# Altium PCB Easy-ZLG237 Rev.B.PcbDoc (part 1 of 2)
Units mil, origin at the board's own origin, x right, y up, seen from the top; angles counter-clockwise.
Board outline 3937.01 x 2559.06 mil, 2 copper layers (Top Layer, Bottom Layer); 111 components, 102 nets, 447 pads, 498 vias.
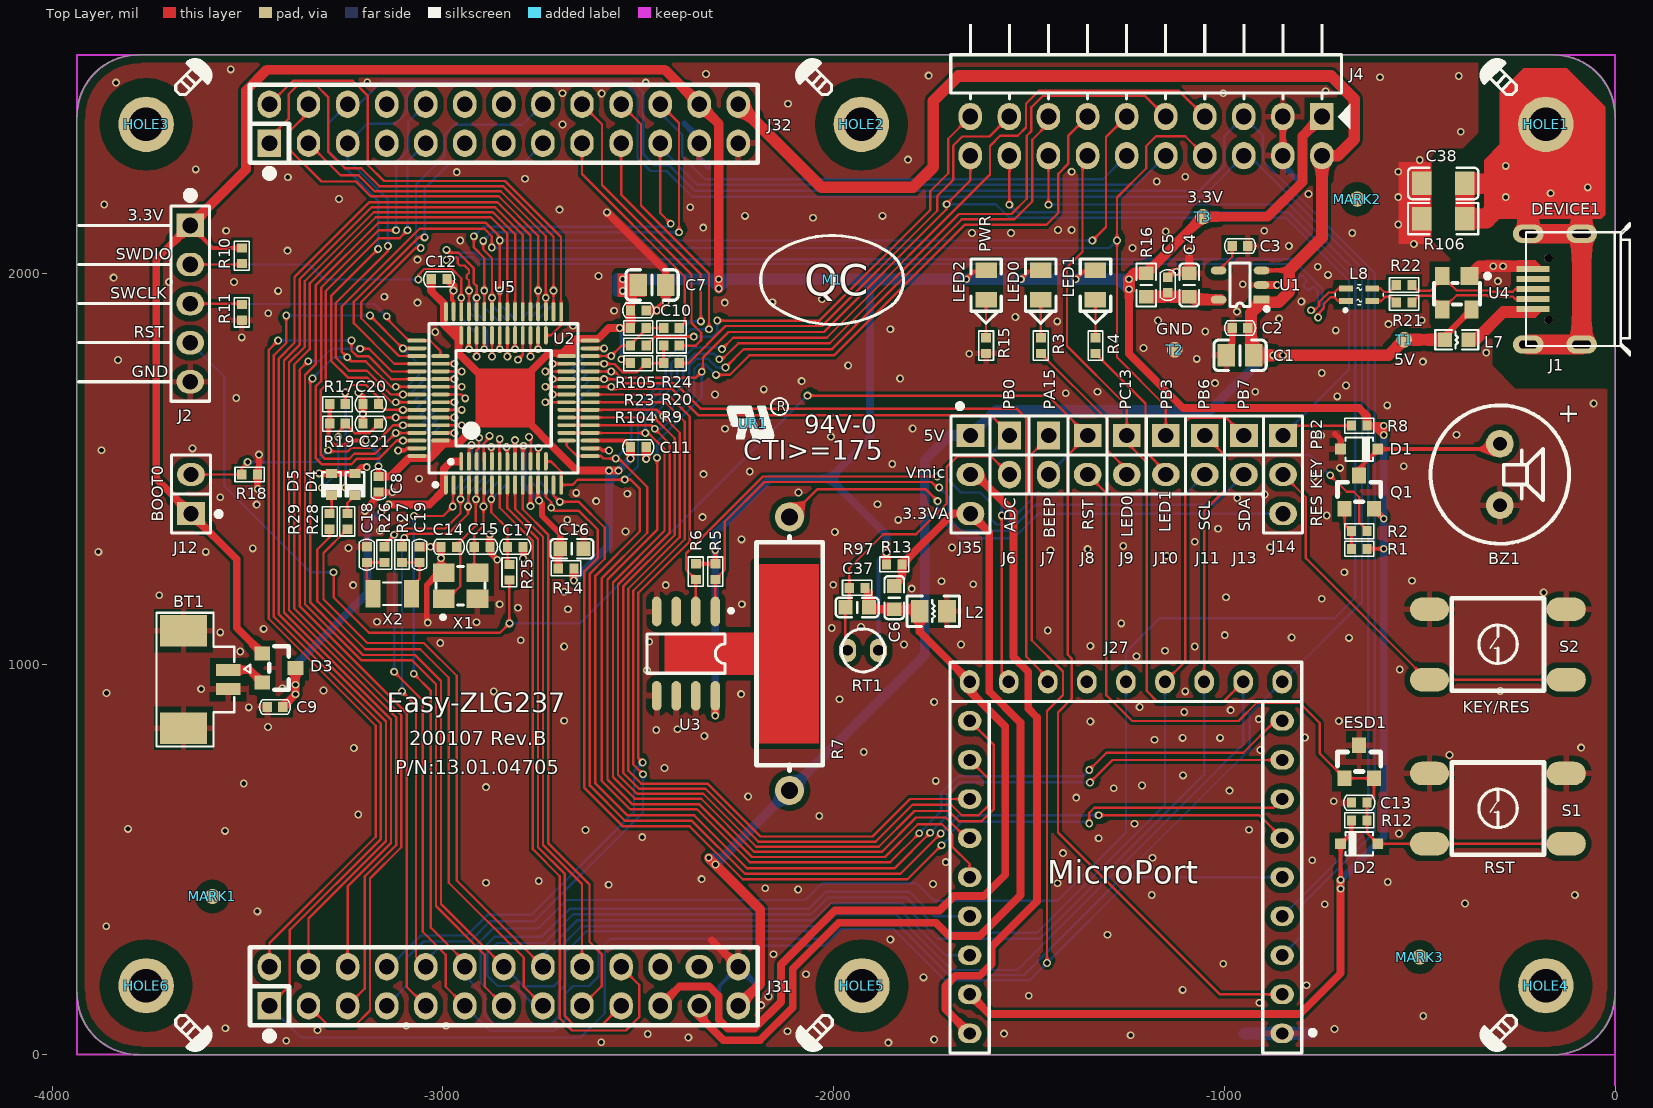
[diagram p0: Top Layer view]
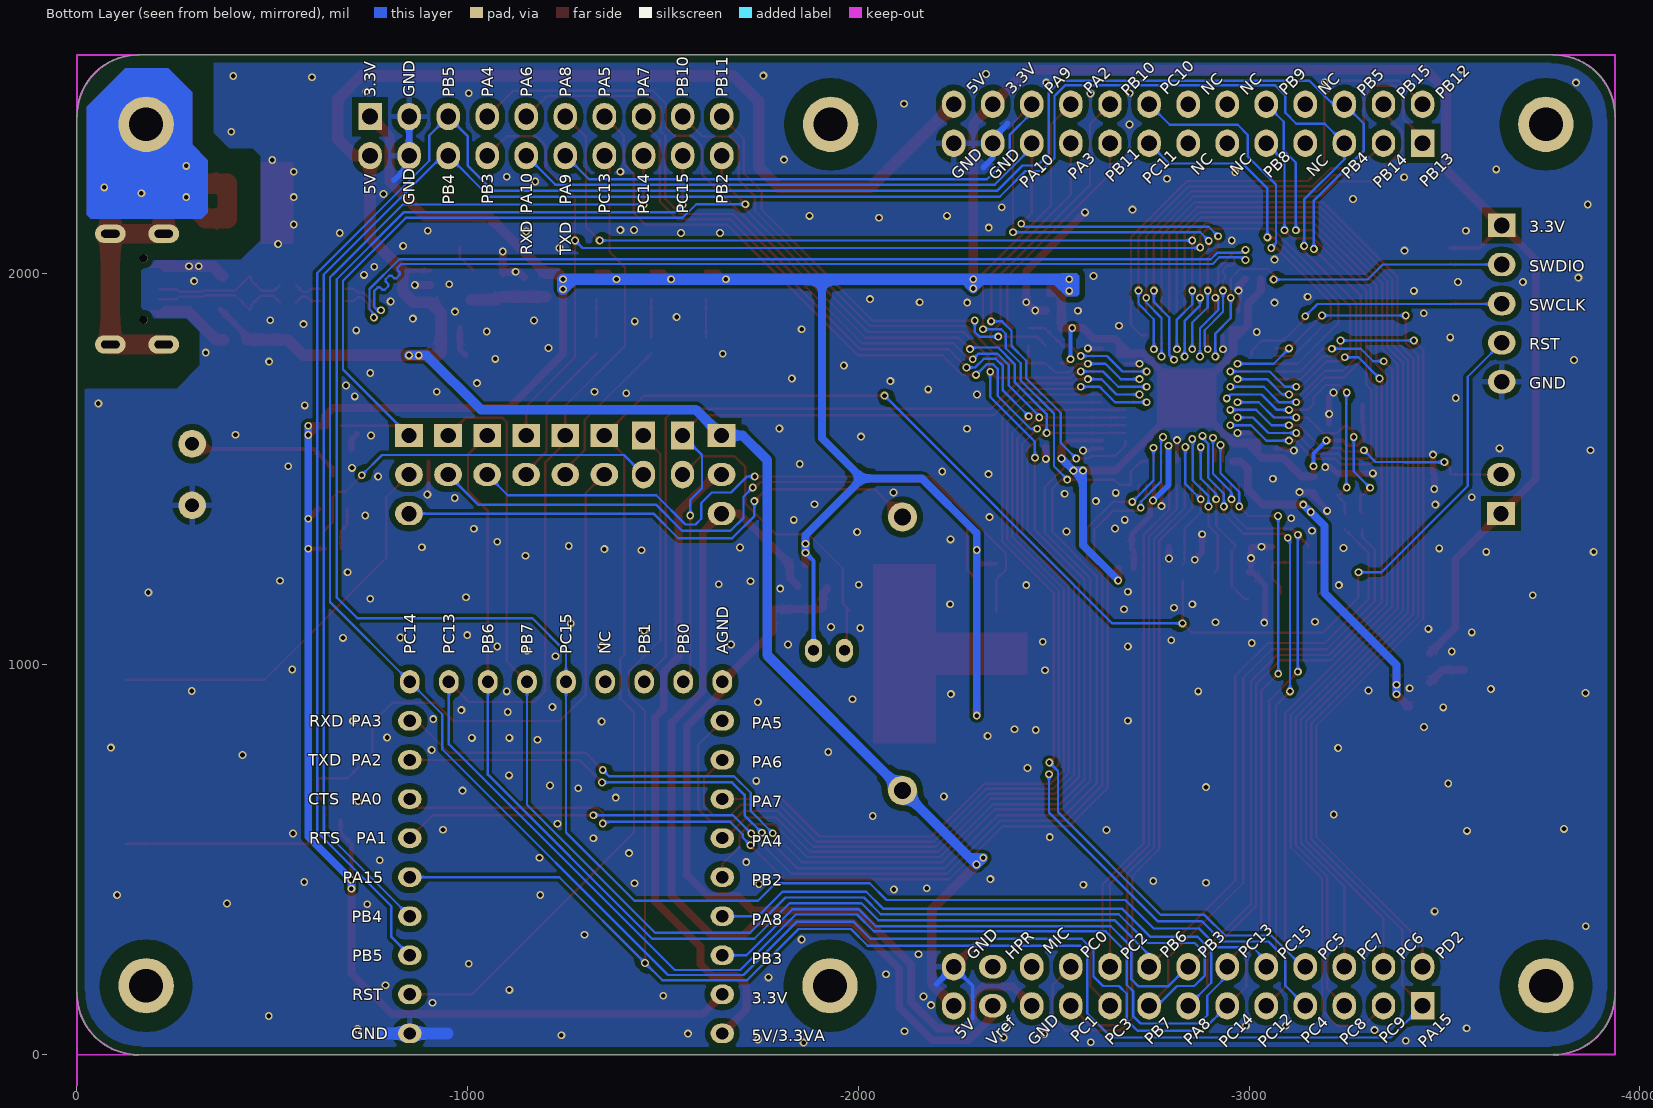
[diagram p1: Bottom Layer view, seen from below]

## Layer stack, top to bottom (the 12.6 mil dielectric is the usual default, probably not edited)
Top Layer: signal copper 1.4
Dielectric: dielectric 12.6, FR-4, Dk 4.8
Bottom Layer: signal copper 1.4

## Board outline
0,2401.58 ccw(c-157.48,2401.58) -157.48,2559.06 -3779.52,2559.06 ccw(c-3779.52,2401.58) -3937,2401.58 -3937.01,2401.58 -3937.01,157.54 ccw(c-3779.53,157.54) -3779.53,0.06 -3779.53,0 -157.48,0 ccw(c-157.48,157.48) 0,157.48

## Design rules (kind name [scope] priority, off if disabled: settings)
Clearance Clearance_Keepout [OnLayer('Keep-Out Layer')] p1: gap=20
Clearance Clearance_Wave [OnLayer('Bottom Layer') and IsSMTPin vs IsPadHoleValid>   (  HasFootprint('PAD-35/50') or  HasFootprint('HOLE-3.2') or  HasFootprint('HOLE-3.2 - Screw') or   HasFootprint('HOLE4.22-SMT') or   HasFootprint('Mou Hole-300D450W310H-SMD') or    HasFootprint('AW6748') or HasFootprint('IDCS80P500W-20X2-F')  )] p2: gap=157.48
Clearance Clearance_Via2Via [IsVia vs IsVia] p3: gap=6
Clearance Clearance_Poly2All [InPoly] p4: gap=15
Clearance Clearance_TP [HasFootprint('PAD-40') vs HasFootprint('PAD-40')] p5: gap=50
Clearance [All] p6: gap=6
DiffPairsRouting [All] p1: maxlimit=6 minlimit=6 mostfreqgap=6 maxuncoupledlength=500
HoleSize [All] p1: absolutevalues=TRUE maxlimit=1000 minlimit=1 maxpercent=80.000 minpercent=20.000
MinimumSolderMaskSliver [All] p1: minsoldermaskwidth=4
PlaneClearance PlaneClearance_Full [IsVia] p1: clearance=9
PlaneClearance [All] p2: clearance=20
PlaneConnect PlaneConnect_Full [IsVia] p1: planeconnectstyle=Direct reliefexpansion=20 reliefentries=4 reliefconductorwidth=10 reliefairgap=10
PlaneConnect [All] p2: planeconnectstyle=Relief reliefexpansion=10 reliefentries=4 reliefconductorwidth=15 reliefairgap=10
PolygonConnect PolygonConnect_SMDHole [HasFootprint('Mou Hole-300D450W310H-SMD') or HasFootprint('Mou Hole-373D600H-SMD')] p1: connectstyle=Relief reliefconductorwidth=80 reliefentries=4 polygonreliefangle="45 Angle"
PolygonConnect PolygonConnect_Full [IsVia or   HasFootprint('PAD-40') or  HasFootprint('PAD-35/50') or  HasFootprint('HOLE-3.2') or   HasFootprint('HOLE-3.2 - Screw')] p2: connectstyle=Direct reliefconductorwidth=10 reliefentries=4 polygonreliefangle="90 Angle"
PolygonConnect [All] p3: connectstyle=Relief reliefconductorwidth=15 reliefentries=4 polygonreliefangle="90 Angle"
RoutingVias [All] p1: holewidth=12 width=20 viastyle="Through Hole" minholewidth=12 minwidth=20 maxholewidth=12 maxwidth=20
SilkToSilkClearance [IsText > HasFootprint('ZY_UR-3X2')] p1: silktosilkclearance=2
SilkscreenOverComponentPads SilkToSolderMaskClearance [IsPad vs IsText] p1: minsilkscreentomaskgap=2
SolderMaskExpansion [All] p1: expansion=4
Width Width_PWR [InNetClass('PWR')] p1: maxlimit=50 minlimit=9.84 preferedwidth=9.84
Width [All] p2: maxlimit=6 minlimit=6 preferedwidth=6
21 further rules are at their usual default settings.

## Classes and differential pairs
component class U_08: BT1 C7 C8 C9 C10 C11 C12 C13 C14 C15 C16 C17 C18 C19 C20 C21 D2 D3 D4 D5 ESD1 J2 J8 J12 R10 R11 R12 R14 R17 R18 R19 R25 R26 R27 R28 R29 R104 R105 S1 U2 U5 X1 X2
component class U_05: J4
component class U_04: J27 J35
net class clk_rst: RST SWCLK/PA14_7
net class PWR: 3.3V 3.3VA 3.3VA_ZLG 5V 5V/3.3VA_MICROP AGND EARTH GND NetBT1_1 NetBZ1_1 NetC4_1 NetJ1_1 VBAT
differential pair USB_1: +USB_1_P -USB_1_N
differential pair USB_DEVICE1_6: +USB_DEVICE1_6_P -USB_DEVICE1_6_N

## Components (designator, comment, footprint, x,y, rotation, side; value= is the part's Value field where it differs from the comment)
BT1 "2P,间距1.25mm" FPC2-49T -3634.25,1063.58 r270 top
BZ1 "BUZZER2" BUZZ-4/9 -295,1485 r270 top
C1 "106" 0805C -960,1790 r180 top
C2 "C1005X5R1C105KT000E,1μF" 0402C -960,1860 r180 top
C3 "0.01μF,±10%" 0402C -960,2070 r0 top
C4 "GRM188R61A475KE15D,4.7uF" 0603C -1090,1970 r90 top
C5 "0.1μF,±10%" 0402C -1145,1970 r90 top
C6 "GRM188R61A475KE15D,4.7uF" 0603C -1845,1170 r270 top
C7 "106" 0805C -2465,1970 r0 top
C8 "0.1μF,±10%" 0402C -3165,1460 r270 top
C9 "0.1μF,±10%" 0402C -3430,890 r180 top
C10 "0.1μF,±10%" 0402C -2500,1905 r0 top
C11 "0.1μF,±10%" 0402C -2500,1555 r0 top
C12 "0.1μF,±10%" 0402C -3010,1985 r0 top
C13 "C1005X5R1C105KT000E,1μF" 0402C -655,645 r180 top
C14 "22pF,±5%" 0402C -2985,1300 r180 top
C15 "22pF,±5%" 0402C -2900,1300 r0 top
C16 "4.7uF" 0603C -2670,1295 r180 top
C17 "0.1μF,±10%" 0402C -2815,1300 r180 top
C18 "10PF,±0.5PF" 0402C -3195,1280 r90 top
C19 "10PF,±0.5PF" 0402C -3060,1280 r90 top
C20 "5PF,±0.25%" 0402C -3185,1665 r180 top
C21 "5PF,±0.25%" 0402C -3185,1615 r180 top
C37 "GRM188R61A475KE15D,4.7uF" 0603C -1940,1145 r0 top
C38 "102,±10%" 1206C -440,2230 r0 top
D1 "DIODE1" SOD-323 -655,1550 r0 top
D2 "DIODE1" SOD-323 -655,540 r180 top
D3 "BAT54C,共阴" SOT-23 -3420,990 r0 top
D4 "PESD5V0S1UB" SOD-523 -3225,1460 r270 top
D5 "PESD5V0S1UB" SOD-523 -3285,1460 r270 top
ESD1 "PESD3V3S2UT" SOT-23 -655,750 r90 top
HOLE1 "HOLE - 螺丝孔" "HOLE-2.2  - Screw" -177.17,2381.37 r90 top locked
HOLE2 "HOLE - 螺丝孔" "HOLE-2.2  - Screw" -1929.13,2381.37 r90 top locked
HOLE3 "HOLE - 螺丝孔" "HOLE-2.2  - Screw" -3759.84,2381.38 r0 top locked
HOLE4 "HOLE - 螺丝孔" "HOLE-2.2  - Screw" -177.17,176.65 r180 top locked
HOLE5 "HOLE - 螺丝孔" "HOLE-2.2  - Screw" -1927.56,176.65 r180 top locked
HOLE6 "HOLE - 螺丝孔" "HOLE-2.2  - Screw" -3759.84,176.65 r270 top locked
J1 "A01SB141B1-261,MicroUSB插座" MICROUSB-5S -1,1959.54 r90 top
J2 "SWD" SIP-5-2.54-6.0-R90 -3647.05,1922.54 r270 top locked
J4 "HEADER 10X2" IDC-20-2.54-R90 -1200.3,2351.23 r180 top locked
J6 "CON2" SIP-2-2.54#1 -1550,1535 r270 top
J7 "CON2" SIP-2-2.54#1 -1450,1535 r270 top
J8 "RST" SIP-2-2.54#2 -1350,1535 r270 top
J9 "LED0" SIP-2-2.54#2 -1250,1535 r270 top
J10 "LED1" SIP-2-2.54#2 -1150,1535 r270 top
J11 "CON2" SIP-2-2.54#2 -1050,1535 r270 top
J12 "BOOT0" SIP-2-2.54#2 -3645,1435 r90 top
J13 "CON2" SIP-2-2.54#2 -950,1535 r270 top
J14 "KEY" SIP-3-2.54 -850,1485 r270 top
J27 "3X7Inter" "SIP-27 2.54C" -752,159.48 r180 top locked
J31 "HEADER 13X2" IDC-26#1 -2844.17,175.15 r0 top locked
J32 "HEADER 13X2" IDC-26#2 -2844.17,2382.87 r0 top locked
J35 "Vol_Sel" SIP-3-2.54 -1650,1485 r270 top
L2 "300Ω,2A" 0805L -1745,1135 r180 top
L7 "600Ω,1A" 0603L -405,1830 r0 top
L8 "DLW21SN900SQ2L" FIL_DLW21S -655,1945 r90 top
LED0 "LED0" LED-0805 -1470,1970 r270 top
LED1 "LED1" LED-0805 -1330,1970 r270 top
LED2 "LED1" LED-0805 -1610,1970 r270 top
M1 "ZY QC" ZY_QC -2004,1983 r0 top
MARK1 "MARKER" MARKER-C-1.0M -3590,405 r180 top
MARK2 "MARKER" MARKER-C-1.0M -660,2190 r180 top
MARK3 "MARKER" MARKER-C-1.0M -500,250 r180 top
Q1 "PNP-1" SOT-23 -655,1440 r90 top
R1 "RTT02103JTH,10K" 0402R -655,1295 r0 top
R2 "1.5K,±1%" 0402R -655,1340 r0 top
R3 "1.5K,±1%" 0402R -1470,1815 r270 top
R4 "1.5K,±1%" 0402R -1330,1815 r270 top
R5 "RTT02103JTH,10K" 0402R -2303.01,1236.48 r90 top
R6 "RTT02103JTH,10K" 0402R -2353.01,1236.48 r90 top
R7 "20Ω,±5%" RESAD1778W80L1450D430P -2113.01,1026.48 r90 top
R8 "RTT02472JTH,4.7K" 0402R -655,1610 r180 top
R9 "0Ω,±5%" 0402R -2415,1770 r0 top
R10 "RTT02103JTH,10K" 0402R -3515,2045 r90 top
R11 "RTT02103JTH,10K" 0402R -3515,1900 r90 top
R12 "RTT02103JTH,10K" 0402R -655,600 r180 top
R13 "10Ω,±0.5%" 0402R -1845,1255 r0 top
R14 "RTT02000JTH,0Ω" 0402R -2685,1245 r180 top
R15 "1.5K,±1%" 0402R -1610,1815 r90 top
R16 "0Ω" 0603R -1200,1970 r90 top
R17 "2K,±1%" 0402R -3270,1665 r180 top
R18 "RTT02103JTH,10K" 0402R -3495,1485 r180 top
R19 "2K,±1%" 0402R -3270,1615 r180 top
R20 "0Ω,±5%" 0402R -2415,1815 r0 top
R21 "22Ω,±5%" 0402R -540,1925 r0 top
R22 "22Ω,±5%" 0402R -540,1970 r180 top
R23 "0Ω,±5%" 0402R -2500,1815 r0 top
R24 "0Ω,±5%" 0402R -2415,1860 r0 top
R25 "0Ω,±5%" 0402R -2830,1235 r90 top
R26 "0Ω,±5%" 0402R -3150,1280 r270 top
R27 "0Ω,±5%" 0402R -3105,1280 r270 top
R28 "0Ω,±5%" 0402R -3245,1365 r270 top
R29 "0Ω,±5%" 0402R -3290,1365 r270 top
R97 "2K,±5%" 0402R -1940,1195 r0 top
R104 "RTT02103JTH,10K" 0402R -2500,1770 r180 top
R105 "RTT02103JTH,10K" 0402R -2500,1860 r180 top
R106 "1MΩ,±1%" 1206R -440,2140 r0 top
RT1 "MF52E-103F3435FB,10KΩ" MF52E-103F3435FB -1925,1035 r270 top
S1 "RST" KEY-6S -300,630 r0 top
S2 "KEY/RES" KEY-6S -300,1050 r0 top
T1 "5V" PAD-40 -540,1830 r270 top
T2 "GND" PAD-40 -1127.01,1804.48 r180 top
T3 "3.3V" PAD-40 -1055,2145 r180 top
U1 "ZL6205A33TS5,SOT-23-5" SOT-23-5 -960,1970 r180 top
U2 "ZLG237P48A" QFP50P900X900X160-48L -2845.01,1680 r90 top locked
U3 "LM75B" SOIC127P600X175-8N -2378.01,1026.48 r270 top
U4 "PRTR5V0U2X" SOT-143 -405,1950 r270 top
U5 "ZLG217P64A" QFP50P1200X1200X160-64L -2845,1680 r90 top locked
UR1 "UR" ZY_UR-3X2 -2207,1616 r0 top
X1 "JYD3A1C7G6-10-12.000,12.0000MHz" OSCCC250X320X80-4N -2955,1200 r0 top
X2 "SC-32S,32.768kHz" XTAL320X150X90 -3130,1180 r180 top

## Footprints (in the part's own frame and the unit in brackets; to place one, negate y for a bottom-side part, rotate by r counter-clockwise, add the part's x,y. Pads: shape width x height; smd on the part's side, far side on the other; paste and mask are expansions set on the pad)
0402C [mm]
  rect 0.6x0.65 smd mask+0.025: 1(-0.508,0) 2(0.508,0)
  silkscreen extent -1.01,-0.48 1.01,0.48, body extent -0.51,-0.23 0.49,0.27, height 0.5
0402R [mm]
  rect 0.6x0.65 smd mask+0.025: 1(-0.508,0) 2(0.508,0)
  silkscreen extent -0.95,-0.48 0.95,0.48, body extent -0.47,-0.25 0.53,0.25, height 0.35
0603C [mm]
  rect 0.9x0.95 smd: 1(-0.762,0) 2(0.762,0)
  silkscreen extent -1.4,-0.64 1.4,0.64, body extent -0.79,-0.38 0.81,0.42, height 0.3
0603L [mm]
  rect 0.9x0.95 smd: 1(-0.762,0) 2(0.762,0)
  silkscreen extent -1.4,-0.64 1.4,0.64, body extent -0.8,-0.4 0.8,0.4, height 0.3
0603R [mm]
  rect 0.9x0.95 smd: 1(-0.762,0) 2(0.762,0)
  silkscreen extent -1.4,-0.64 1.4,0.64, body extent -0.8,-0.4 0.8,0.4, height 0.3
0805C [mm]
  rect 1.15x1.45 smd: 1(-0.889,0) 2(0.889,0)
  silkscreen extent -1.7,-0.99 1.7,0.99, body extent -1,-0.63 1,0.63, height 0.78
0805L [mm]
  rect 1.15x1.45 smd: 1(-0.889,0) 2(0.889,0)
  silkscreen extent -1.7,-0.99 1.7,0.99, body extent -1.02,-0.64 0.98,0.62, height 0.55
1206C [mil] "元件 长X宽=120X60mil"
  rect 50x60 smd: 1(-55,0) 2(55,0)
  silkscreen extent -90,-40 90,40, body extent -62,-32 64,31, height 39
1206R [mil] "元件 长X宽=120X60mil"
  rect 50x60 smd: 1(-55,0) 2(55,0)
  silkscreen extent -90,-40 90,40, body extent -63,-31 63,31, height 24
BUZZ-4/9 [mm] "工制单位"
  round 1.8 hole 0.9: 1(-2,0) 2(2,0)
  silkscreen extent -4.5,-4.5 4.5,4.5
FIL_DLW21S [mm] "共模扼流圈"
  rect 0.4x0.9 smd paste-0.2: 1(-0.4,0.85) 2(-0.4,-0.85) 3(0.4,-0.85) 4(0.4,0.85)
  Top Layer pour cut-out: -0.981,0.4 0.981,0.4 0.981,-0.4 -0.981,-0.4
  silkscreen extent -1.1,-1.55 0.65,1.55
FPC2-49T [mil]
  rect 31x63 smd: 1(78.58,84.25) 2(127.79,84.25)
  rect 80x120 smd: 2(-21.82,-29.93) 2(228.18,-29.93)
  silkscreen extent -68,-99 275,141
"HOLE-2.2  - Screw" [mm]
  round 3.6 hole 2.2: 1(0,0)
  silkscreen extent 1.93,1.93 4.22,4.22
IDC-20-2.54-R90 [mil] "Connector; Header; 10x2 Position"
  rect 60x70 hole 40: 1(-450,-50)
  oval 60x70 hole 40: 2(-450,50) 3(-350,-50) 4(-350,50) 5(-250,-50) 6(-250,50) 7(-150,-50) 8(-150,50) 9(-50,-50) 10(-50,50) 11(50,-50) 12(50,50) 13(150,-50) 14(150,50) 15(250,-50) 16(250,50) 17(350,-50) 18(350,50) 19(450,-50) 20(450,50)
  silkscreen extent -522,-444 500,-17
IDC-26#1 [mil]
  rect 60x70 hole 40: 1(-600,-50)
  oval 60x70 hole 40: 2(-600,50) 3(-500,-50) 4(-500,50) 5(-400,-50) 6(-400,50) 7(-300,-50) 8(-300,50) 9(-200,-50) 10(-200,50) 11(-100,-50) 12(-100,50) 13(0,-50) 14(0,50) 15(100,-50) 16(100,50) 17(200,-50) 18(200,50) 19(300,-50) 20(300,50) 21(400,-50) 22(400,50) 25(600,-50) 26(600,50)
  round 60 / inner oval 70x60 / far side oval 70x60 hole 40: 23(500,-50)
  oval 70x60 hole 40: 24(500,50)
  silkscreen extent -650,-136 650,100, body extent -650,-100 650,100, height 298
IDC-26#2 [mil]
  rect 60x70 hole 40: 1(-600,-50)
  oval 60x70 hole 40: 2(-600,50) 3(-500,-50) 4(-500,50) 5(-400,-50) 6(-400,50) 7(-300,-50) 8(-300,50) 9(-200,-50) 10(-200,50) 11(-100,-50) 12(-100,50) 13(0,-50) 14(0,50) 15(100,-50) 16(100,50) 17(200,-50) 18(200,50) 19(300,-50) 20(300,50) 21(400,-50) 22(400,50) 23(500,-50) 24(500,50) 25(600,-50) 26(600,50)
  silkscreen extent -650,-136 650,100, body extent -650,-100 650,100, height 298
KEY-6S [mil]
  oval 100x60 smd: 1(-175,90) 2(-175,-90) 3(175,-90) 4(175,90)
  silkscreen extent -118,-118 118,118, body extent -201,-122 201,122, height 268
LED-0805 [mm] "170907内距改0.9mm"
  rect 1.014x1.4 smd: 1(-0.957,0) 2(0.957,0)
  silkscreen extent -1.7,-0.99 2.49,0.99, body extent -1,-0.64 1,0.64, height 1.1
MARKER-C-1.0M [mm]
  round 1 smd paste-1.016 mask+0.5: 0(0,0)
  Top Layer pour cut-out: -1.1,0 -1.016,-0.421 -0.778,-0.778 -0.421,-1.016 0,-1.1 0,-1.1 0.421,-1.016 0.778,-0.778 1.016,-0.421 1.1,0 1.1,0 1.016,0.421 0.778,0.778 0.421,1.016 0,1.1 0,1.1 -0.421,1.016 -0.778,0.778 -1.016,0.421 -1.1,0
MF52E-103F3435FB [mm]
  oval 1.5x1.1 hole 0.7: 1(0,1) 2(0,-1)
  silkscreen extent -1.4,-1.4 1.4,1.4
MICROUSB-5S [mm]
  oval 1.2x2 on Top Paste: 0(-3.6,2.15) 0(-3.6,5.62) 0(3.6,2.15) 0(3.6,5.62)
  round 0.54 hole 0.55 unplated: 0(-2,4.3) 0(2,4.3)
  rect 0.4x2.15 smd: 1(-1.3,5.31) 2(-0.65,5.31) 3(0,5.31) 4(0.65,5.31) 5(1.3,5.31)
  oval 1.2x2 hole 0.5 slot 1.2 at 90 deg: 6(-3.6,5.62) 7(3.6,5.62) 8(-3.6,2.15) 9(3.6,2.15)
  silkscreen extent -4.3,-0.99 4.3,5.77
OSCCC250X320X80-4N [mm]
  rect 1.4x1.2 smd: 1(-1.1,-0.85) 2(1.1,-0.85) 3(1.1,0.85) 4(-1.1,0.85)
  silkscreen extent -1.6,-2.16 1.6,1.25
PAD-40 [mil]
  round 40 smd paste-43.31: 1(0,0)
QFP50P900X900X160-48L [mm] "QFP, 48-Leads, Body 7.00x7.00mm, Pitch 0.50mm, IPC High Density"
  oval 1.2x0.25 smd mask+0.051: 1(-4.1,2.75) 2(-4.1,2.25) 3(-4.1,1.75) 4(-4.1,1.25) 5(-4.1,0.75) 6(-4.1,0.25) 7(-4.1,-0.25) 8(-4.1,-0.75) 9(-4.1,-1.25) 10(-4.1,-1.75) 11(-4.1,-2.25) 12(-4.1,-2.75) 25(4.1,-2.75) 26(4.1,-2.25) 27(4.1,-1.75) 28(4.1,-1.25) 29(4.1,-0.75) 30(4.1,-0.25) 31(4.1,0.25) 32(4.1,0.75) 33(4.1,1.25) 34(4.1,1.75) 35(4.1,2.25) 36(4.1,2.75)
  oval 0.25x1.2 smd mask+0.051: 13(-2.75,-4.1) 14(-2.25,-4.1) 15(-1.75,-4.1) 16(-1.25,-4.1) 17(-0.75,-4.1) 18(-0.25,-4.1) 19(0.25,-4.1) 20(0.75,-4.1) 21(1.25,-4.1) 22(1.75,-4.1) 23(2.25,-4.1) 24(2.75,-4.1) 37(2.75,4.1) 38(2.25,4.1) 39(1.75,4.1) 40(1.25,4.1) 41(0.75,4.1) 42(0.25,4.1) 43(-0.25,4.1) 44(-0.75,4.1) 45(-1.25,4.1) 46(-1.75,4.1) 47(-2.25,4.1) 48(-2.75,4.1)
  silkscreen extent -4.25,-3.1 3.1,3.55, body extent -3.5,-3.5 3.5,3.5, height 1.6
QFP50P1200X1200X160-64L [mm] "QFP, 64-Leads, Body 10.00x10.00mm, Pitch 0.50mm, IPC High Density"
  oval 1.25x0.25 smd mask+0.051: 1(-5.625,3.75) 2(-5.625,3.25) 3(-5.625,2.75) 4(-5.625,2.25) 5(-5.625,1.75) 6(-5.625,1.25) 7(-5.625,0.75) 8(-5.625,0.25) 9(-5.625,-0.25) 10(-5.625,-0.75) 11(-5.625,-1.25) 12(-5.625,-1.75) 13(-5.625,-2.25) 14(-5.625,-2.75) 15(-5.625,-3.25) 16(-5.625,-3.75) 33(5.625,-3.75) 34(5.625,-3.25) 35(5.625,-2.75) 36(5.625,-2.25) 37(5.625,-1.75) 38(5.625,-1.25) 39(5.625,-0.75) 40(5.625,-0.25) 41(5.625,0.25) 42(5.625,0.75) 43(5.625,1.25) 44(5.625,1.75) 45(5.625,2.25) 46(5.625,2.75) 47(5.625,3.25) 48(5.625,3.75)
  oval 0.25x1.25 smd mask+0.051: 17(-3.75,-5.625) 18(-3.25,-5.625) 19(-2.75,-5.625) 20(-2.25,-5.625) 21(-1.75,-5.625) 22(-1.25,-5.625) 23(-0.75,-5.625) 24(-0.25,-5.625) 25(0.25,-5.625) 26(0.75,-5.625) 27(1.25,-5.625) 28(1.75,-5.625) 29(2.25,-5.625) 30(2.75,-5.625) 31(3.25,-5.625) 32(3.75,-5.625) 49(3.75,5.625) 50(3.25,5.625) 51(2.75,5.625) 52(2.25,5.625) 53(1.75,5.625) 54(1.25,5.625) 55(0.75,5.625) 56(0.25,5.625) 57(-0.25,5.625) 58(-0.75,5.625) 59(-1.25,5.625) 60(-1.75,5.625) 61(-2.25,5.625) 62(-2.75,5.625) 63(-3.25,5.625) 64(-3.75,5.625)
  silkscreen extent -5.75,-4.85 4.85,4.85, body extent -5,-5 5,5, height 1.6
RESAD1778W80L1450D430P [mm]
  round 1.9 hole 1.1: 1(-8.89,0) 2(8.89,0)
  silkscreen extent -7.62,-2.15 7.62,2.15
SIP-2-2.54#1 [mm]
  rect 1.8x1.5 hole 1: 1(-1.27,0)
  oval 1.8x1.5 hole 1: 2(1.27,0)
  silkscreen extent -2.54,-1.27 2.54,1.27, body extent -2.54,-1.27 2.54,1.27, height 7.58
SIP-2-2.54#2 [mm]
  rect 1.5x1.8 hole 1: 1(-1.27,0)
  oval 1.5x1.8 hole 1: 2(1.27,0)
  silkscreen extent -2.54,-1.27 2.54,1.27, body extent -2.54,-1.27 2.54,1.27, height 7.58
SIP-3-2.54 [mm]
  rect 1.5x1.8 hole 1: 1(-2.54,0)
  oval 1.5x1.8 hole 1: 2(0,0) 3(2.54,0)
  silkscreen extent -3.81,-1.27 3.81,1.27, body extent -3.81,-1.27 3.81,1.27, height 7.58
SIP-5-2.54-6.0-R90 [mil] "引脚伸出部分为6.0mm"
  rect 60x70 hole 40: 1(-200,0)
  oval 60x70 hole 40: 2(-100,0) 3(0,0) 4(100,0) 5(200,0)
  silkscreen extent -286,-285 250,49
"SIP-27 2.54C" [mil]
  oval 60x50 hole 31.5: 1(100,105) 2(100,5) 3(100,-95) 4(100,-195) 5(100,-295) 6(100,-395) 7(100,-495) 8(100,-595) 9(100,-695) 19(900,-695) 20(900,-595) 21(900,-495) 22(900,-395) 23(900,-295) 24(900,-195) 25(900,-95) 26(900,5) 27(900,105)
  oval 50x60 hole 31.5: 10(100,-795) 11(200,-795) 12(300,-795) 13(400,-795) 14(500,-795) 15(600,-795) 16(700,-795) 17(800,-795) 18(900,-795)
  silkscreen extent 17,-845 950,155
SOD-323 [mil]
  rect 28x28 smd: 1(-47.5,0) 2(47.5,0)
  silkscreen extent -35,-30 35,30, body extent -51,-26 51,25, height 39
SOD-523 [mm] "依手册推荐封装制作，未验证"
  rect 0.6x0.7 smd: 1(-0.71,0) 2(0.71,0)
  silkscreen extent -0.78,-0.61 0.78,0.64
SOIC127P600X175-8N [mil]
  oval 76.06x24 smd: 1(-108.03,75) 2(-108.03,25) 3(-108.03,-25) 4(-108.03,-75) 5(108.03,-75) 6(108.03,-25) 7(108.03,25) 8(108.03,75)
  silkscreen extent -115,-100 50,120, body extent -118,-96 118,97, height 61
SOT-23 [mil]
  rect 40x36 smd: 1(-42.5,37.4) 2(-42.5,-37.4) 3(42.5,0)
  silkscreen extent -25,-56 25,56, body extent -47,-57 50,58, height 39
SOT-23-5 [mil]
  rect 40x20 smd: 1(-55,37.4)
  oval 40x20 smd: 2(-55,0) 3(-55,-37.4) 4(55,-37.4) 5(55,37.4)
  silkscreen extent -73,-57 26,66, body extent -55,-57 55,57, height 43
SOT-143 [mil] "SOT-143B"
  rect 46x46 smd: 1(-43,32.5)
  rect 46x36 smd: 2(-43,-37.5) 3(43,-37.5) 4(43,37.5)
  silkscreen extent -49,-59 30,84
XTAL320X150X90 [mm]
  rect 1x1.8 smd: 1(-1.253,0) 2(1.25,0)
  silkscreen extent -0.58,-0.74 0.58,0.74
ZY_QC [mil]
  silkscreen extent -183,-114 183,114
ZY_UR-3X2 [mil]
  silkscreen extent -67,-40 90,65

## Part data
BT1: library part 1.10.05.0281, "2P,间距1.25mm,Wafer凹槽边框,90°,WCON"
BZ1: library part 1.06.09.0016, "Buzzer有极性"
C1 C7: library part 1.02.02.0055, "106,10μF,±10%,10V,X5R,0805,RoHS"
C2 C13: library part 1.02.17.0092, "C1005X5R1C105KT000E,1μF,±10%,16V,X5R,0402,TDK,RoHS"
C3: library part 1.02.17.0019, "GRM155R71H103KA88D,0.01μF,±10%,50V,X7R,0402,muRata,RoHS"
C4 C6 C16 C37: library part 1.02.01.0080, "GRM188R61A475KE15D,4.7uF,±10%,10V,X5R,0603,muRata,RoHS"
C5 C8 C9 C10 C11 C12 C17: library part 1.02.17.0006, "0.1μF,±10%,16V,X7R,0402,RoHS"
C14 C15: library part 1.02.17.0036, "GRM1555C1H220JA01D,22pF,±5%,50V,C0G,0402,muRata,RoHS"
C18 C19: library part 1.02.17.0008, "GRM1555C1H100JA01D,10PF,±0.5PF,50V,COG,0402,muRata,RoHS"
C20 C21: library part 1.02.17.0043, "5PF,±0.25%,50V,COG,GRM1555C1H5R0CA01D,0402,RoHS"
C38: library part 1.02.03.0003, "102,±10%,2KV,X7R,1206,*,RoHS"
D1 D2: library part 1.04.07.0027, "1N4148,SOD-323,RoHS"
D3: library part 1.04.07.0033, "BAT54C,共阴,200mA,30V,SOT-23-3,NXP,RoHS"
D4 D5: library part 1.04.03.0050, "PESD5V0S1UB,SOD-523,Nexperia"
ESD1: library part 1.05.10.0361, "PESD3V3S2UT,SOT-23,NXP,RoHS"
J1: library part 1.10.12.0014, "A01SB141B1-261,MicroUSB插座,SMT,艾立信,RoHS"
J2: library part CON5, "Connector"
J6 J7 J11 J13: "Connector"
J8 J9 J10 J12: library part CON2, "Connector"
J14 J35: library part CON3, "Connector"
L2: library part 1.03.03.0010, "300Ω,2A,DCR80mΩ,BH05Y354S-300R,SMD,0805,丰晶,RoHS"
L7: library part 1.03.03.0012, "600Ω,1A,DCR200mΩ,BH03Y314S-600R,SMD,0603,丰晶,RoHS"
L8: library part 1.03.01.0113, "DLW21SN900SQ2L,SLN4-0805,村田,RoHS"
LED0 LED1: library part 1.04.05.0002, "绿色,0805,0805,RoHS"
LED2: library part 1.04.05.0001, "红色,0805,0805,RoHS"
Q1: library part 1.04.09.0002, "PNP Transistor"
R1 R5 R6 R10 R11 R12 R18 R104 R105: library part 1.01.17.0006, "RTT02103JTH,10K,±5%,0402,RALEC,RoHS"
R2 R3 R4 R15: library part 1.01.17.0011, "1.5K,±1%,0402,RALEC,RoHS"
R7: library part 1.01.10.0003, "20Ω,±5%,2W,Ф5.5×16mm,RoHS"
R8: library part 1.01.17.0019, "RTT02472JTH,4.7K,±5%,0402,RALEC,RoHS"
R9 R20 R23 R24 R25 R26 R27 R28 R29: library part 1.01.17.0004, "0Ω,±5%,0402,RALEC,RoHS"
R13: library part 1.01.17.0049, "10Ω,±0.5%,0402,RoHS"
R14: library part 1.01.17.0004, "RTT02000JTH,0Ω,±5%,0402,RALEC,RoHS"
R16: library part 1.01.01.0001
R17 R19: library part 1.01.17.0064, "2K,±1%,1/16W,0402,RoHS"
R21 R22: library part 1.01.17.0023, "22Ω,±5%,0402,RALEC,RoHS"
R97: library part 1.01.17.0032, "2K,±5%,0402,RALEC,RoHS"
R106: library part 1.01.03.0024, "1MΩ,±1%,1206,RoHS"
RT1: library part 1.01.14.0023, "MF52E-103F3435FB,10KΩ,THT,安培龙"
S1 S2: library part 1.09.01.0003, "6×6×5.0mm,黑色,SMD,,*"
T1 T2 T3: library part TEST-DOT
U1: library part 08.09.03069, "ZL6205A33TS5,SOT-23-5,ZLG"
U3: library part 1.05.10.0602, "LM75BD,SO-9,NXP,RoHS"
U4: library part 1.05.10.0153, "PRTR5V0U2X,SOT-143B,NXP,RoHS"
U5: library part 1.05.02.0207, "ZLG217P64A,LQFP64,ZLG"
X1: library part 1.07.01.0032, "JYD3A1C7G6-10-12.000,12.0000MHz,±10ppm,10pF,-40~85℃,±10ppm,SMD3225,*,JYEG,RoHS"
X2: library part 1.07.02.0056, "SC-32S,32.768kHz,12.5pF,±20ppm,SMD3215,SII,RoHS,金属"

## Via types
v1: diameter 20, hole 12, Top Layer to Bottom Layer, tented both sides, 498 vias

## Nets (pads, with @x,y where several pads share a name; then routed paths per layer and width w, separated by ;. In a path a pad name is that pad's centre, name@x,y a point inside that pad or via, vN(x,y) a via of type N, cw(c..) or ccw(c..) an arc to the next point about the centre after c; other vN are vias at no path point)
3.3V: C7.1 C8.1 C10.1 C11.1 C12.1 D2.2 D3.1 J2.1 J4.1 J12.1 J27.26 J32.24 LED0.1 LED1.1 LED2.1 Q1.2 R1.2 R5.2 R6.2 R8.1 R10.2 R12.2 R13.1 R14.1 R16.2 R17.2 R19.2 R104.2 R105.2 RT1.1 T3.1 U2.24 U2.36 U2.48 U3.8 U5.19 U5.32 U5.48 U5.64 | length 14320.2
  Top Layer w9.84: J2.1@-3647.05,2122.54 -3589.52,2065 R10.2@-3515,2065 ; C8.1@-3165,1480 v1(-3165,1506) ; U5.19@-2623.54,1571.73 -2536.73,1571.73 C11.1@-2520,1555 ; v1(-2543,1780) -2533,1770 R104.2@-2520,1770 ; R6.2@-2353.01,1256.48 R5.2@-2303.01,1256.48 v1(-2303.01,1291.99) ; v1(-1661,1985) -1641,2005 LED2.1@-1610,2005 ; v1(-1521,1985) -1501,2005 LED0.1@-1470,2005 ; v1(-1381,1985) -1361,2005 LED1.1@-1330,2005 ; v1(-702.5,447.5) D2.2@-702.5,540 -675,567.5 R12.2@-675,600 ; R1.2@-635,1295 v1(-592,1295)
  Top Layer w10: R17.2@-3290,1665 R19.2@-3290,1615 -3293,1612 -3293,1576 -3277,1560 -3252,1560 -3240,1572 v1(-3198,1572)
  Top Layer w15: Q1.2@-617.6,1397.5 v1(-592,1371.9)
  Top Layer w20: J2.1@-3647.05,2122.54 -3734,2035.59 -3734,1474 J12.1@-3645,1385 -3528,1268 -3528,1092.9 D3.1@-3462.5,1027.4 ; C8.1@-3165,1480 -3134.41,1480 -3087.01,1527.4 -3033.31,1527.4 -2996.01,1564.7 -2960.31,1564.7 -2845.01,1680.01 -2960.3,1795.3 -2960.3,1831 -2997.6,1868.3 -2997.6,1922 -3030,1954.4 C12.1@-3030,1985 ; -2845,1680 -2729.7,1795.29 -2694,1795.29 -2656.7,1832.59 -2603,1832.59 -2575.59,1860 R105.2@-2520,1860 ; -2842.23,1680 -2657.23,1495 v1(-2575,1495) v1(-2551,1495) ; v1(-2665,1214) R14.1@-2665,1245 ; v1(-2520,1526) C11.1@-2520,1555 ; v1(-2303.01,868.01) U3.8@-2303.01,918.45 ; R13.1@-1865,1255 v1(-1865,1285) v1(-1865,1308) ; J27.26@-1652,154.48 -1601.52,104 -807,104 -702.5,208.5 v1(-702.5,425) v1(-702.5,447.5) ; v1(-1244,1959) -1244,1794 -1105,1655 -655,1655 -635,1635 R8.1@-635,1610 -616,1610 ; -616,1610 v1(-592,1610) v1(-592,1586) -616,1610
  Top Layer w23: R105.2@-2520,1860 C10.1@-2520,1905 C7.1@-2520,1946 ; C7.1@-2500,1955 C7.1@-2500,1970
  Top Layer w25: J2.1@-3647.05,2122.54 -3504,2265.59 -3504,2468 -3451,2521 -2432.3,2521 J32.24@-2344.17,2432.87 -2294,2382.7 v1(-2294,1985) v1(-2294,1961) ; R16.2@-1200,2000 T3.1@-1055,2145 -889,2145 -800,2234 -800,2351.53 J4.1@-750.3,2401.23
  Top Layer w30: v1(-1244,1959) v1(-1244,1985) -1229,2000 R16.2@-1200,2000
  Bottom Layer w9.84: v1(-3198,1572) -3165,1539 v1(-3165,1506) ; v1(-2547.8,1860) -2543,1855.2 v1(-2543,1780) ; RT1.1@-1885.63,1035 -1885.63,1264.37 v1(-1865,1285)
  Bottom Layer w20: v1(-2665,1214) -2575,1304 -2575,1471 ; v1(-2520,1526) v1(-2551,1495) ; v1(-2303.01,868.01) v1(-2303.01,1291.99) -2303.01,1334.99 -2163,1475 -2010,1475 ; -1907,1985 -1907,1578 -2010,1475 ; v1(-1865,1285) -1865,1330 -2010,1475 ; v1(-702.5,425) v1(-702.5,447.5) -592,558 v1(-592,1295) v1(-592,1371.9) v1(-592,1586) v1(-592,1610) ; -2575,1471 v1(-2551,1495) ; -2575,1471 v1(-2575,1495) v1(-2551,1495)
  Bottom Layer w25: -2318,1985 v1(-2294,1961) ; v1(-2294,1985) v1(-2294,1961) ; -2270,1985 v1(-2294,1961)
  Bottom Layer w30: v1(-2540,1985) -2318,1985 v1(-2294,1985) -2270,1985 -1907,1985 v1(-1661,1985) v1(-1521,1985) v1(-1381,1985) -1270,1985 ; -1270,1985 v1(-1244,1985) v1(-1244,1959) -1270,1985
  other v1: -2540,1955
3.3VA: C6.1 J31.23 J35.3 R13.2 | length 2435.9
  Top Layer w20: J31.23@-2344.17,125.15 -2344.17,99.17 -2282,37 -2189,37 -2105,121 -2105,220 -1987,338 -1738,338 -1704,304 -1626,304 -1522,408 -1522,850 -1602,930 -1602,1337 J35.3@-1650,1385 -1695,1385 R13.2@-1825,1255 -1825,1220 C6.1@-1845,1200
3.3VA_ZLG: C16.2 R14.2 U2.9 U5.13 | length 421.5
  Top Layer w9.84: U2.9@-2795.79,1518.58 v1@-2795.79,1554.58 ; v1@-2756.42,1422.55 U5.13@-2756.42,1458.54
  Top Layer w15: v1(-2754.42,1418.55) -2747,1411.13 -2747,1380 -2700,1333 C16.2@-2700,1300 ; R14.2@-2705,1245 -2705,1290 C16.2@-2700,1295
  Bottom Layer w15: v1(-2793.79,1558.58) -2793.79,1457.92 v1(-2754.42,1418.55)
5V: C1.1 C2.1 J4.2 J31.25 J32.26 J35.1 L7.1 R7.1 T1.1 U1.1 U1.3 U4.4 | length 6213.6
  Top Layer w9.84: U1.3@-905,2007.4 -834,2007.4
  Top Layer w15: L7.1@-435,1830 -435,1840 -368,1907 U4.4@-367.5,1907
  Top Layer w25: v1@-2319.74,503.74 -2188,372 -2188,181.32 J31.25@-2244.17,125.15
  Top Layer w30: J32.26@-2244.17,2432.87 -2031.3,2220 -1797,2220 -1745,2272 -1745,2441 -1681,2505 -727,2505 -668,2446 -668,2343 -709.77,2301.23 J4.2@-750.3,2301.23 -750.3,2091.1 -834,2007.4 -834,1953 -861,1926 -905,1926 -932,1899 -932,1797 C1.1@-925,1790 -580,1790 T1.1@-540,1830 L7.1@-435,1830
  Bottom Layer w25: -2280.75,508.75 -2285.49,504 ; v1(-850,1790) v1(-875,1790) -895,1790 -1034,1651 -1584,1651 J35.1@-1650,1585 -1704,1585 -1767,1522 -1767,1022.49 R7.1@-2113.01,676.48 -2285.49,504 ; -2285.49,504 v1(-2302.75,486.75) v1(-2320,504) -2285.49,504
5V/3.3VA_MICROP: J27.27 J35.2 | length 1668.1
  Top Layer w20: J27.27@-1652,54.48 -1714,116.48 -1714,176 -1688,202 -1626,202 -1596,232 -1596,276 -1480,392 -1480,864 -1502,886 -1502,980 -1540,1018 -1540,1389 -1636,1485 J35.2@-1650,1485
ADC_3: C37.1 J6.2 R97.1 RT1.2 | length 833.1
  Top Layer w6: C37.1@-1979.37,1135.63 C37.1@-1970,1145 ; RT1.2@-1964.37,1035 -1970,1040.63 C37.1@-1970,1145 ; J6.2@-1550,1485 -1597,1532 -1683,1532 -1711,1504 -1711,1410 -1789,1332 -1873,1332 -1960,1245 R97.1@-1960,1195 -1960,1155 C37.1@-1970,1145
AGND: C6.2 C37.2 J27.18 J31.21 L2.2 R97.2 | length 2156.1
  Top Layer w20: J31.21@-2444.17,125.15 -2394.32,175 -2319,175 -2294,150 -2294,90 -2271,67 -2203,67 -2135,135 -2135,231 -1997,369 -1729,369 -1692,406 -1616,406 -1561,461 -1561,840 -1652,931 J27.18@-1652,954.48 -1780,1082.48 L2.2@-1780,1135 -1785,1140 C6.2@-1845,1140 -1905,1140 C37.2@-1910,1145 -1910,1182 -1920,1192 R97.2@-1920,1195
BEEP_3: J7.2 R2.2 | length 955.7
  Top Layer w6: v1(-729,1483) -687,1441 -669,1441 -655,1427 -655,1363 -635,1343 R2.2@-635,1340
  Bottom Layer w6: J7.2@-1450,1485 -1400,1535 -781,1535 v1(-729,1483)
BOOT0_7: J12.2 R18.2 U2.44 U5.60 | length 967.2
  Top Layer w6: J12.2@-3645,1485 R18.2@-3515,1485 -3515,1502 v1(-3500,1517) ; v1(-3294,1547) v1@-3291,1547 ; v1@-3293,1549 v1@-3291,1547 ; U5.60@-3066.46,1611.1 v1(-3102.45,1611.1) -3127.95,1611.1 -3139.77,1599.29 -3139.77,1599.23 -3186,1553 -3235,1553 -3244,1544 -3288,1544 v1@-3291,1547 ; U2.44@-3006.42,1650.47 v1(-2952.11,1650.47)
  Bottom Layer w6: v1(-3500,1517) -3324,1517 v1(-3294,1547) ; v1@-3496,1516 -3398,1516 ; v1@-3294.5,1547.5 v1@-3293,1549 ; v1(-3102.45,1611.1) -3057.9,1611.1 -3018.53,1650.47 v1(-2952.11,1650.47)
CAN0_RX_AWORKS: J32.9 U2.45 U5.61 | length 1421
  Top Layer w6: v1(-3091,2110) -3111,2090 -3164.87,2090 -3300,1954.87 -3300,1714 -3313,1701 -3313,1536 -3302,1525 -3240,1525 -3227,1538 -3174.19,1538 v1(-3120.77,1591.42) U5.61@-3066.46,1591.42 ; U2.45@-3006.42,1630.78 v1(-2970.43,1630.78)
  Bottom Layer w6: v1(-3120.77,1591.42) -3049.58,1591.42 -3010.22,1630.78 v1(-2970.43,1630.78) ; v1(-3091,2110) -3091,2286.04 J32.9@-3044.17,2332.87
CAN0_TX_AWORKS: J32.10 U2.46 U5.62 | length 1561.2
  Top Layer w6: v1(-3120,2110) -3164.97,2110 -3312,1962.97 -3312,1724 -3326,1710 -3326,1527 -3310,1511 -3235,1511 -3221,1525 -3165,1525 -3118.27,1571.73 v1(-3102.45,1571.73) U5.62@-3066.46,1571.73 ; U2.46@-3006.42,1611.1 v1(-2952.11,1611.1)
  Bottom Layer w6: v1(-3120,2110) -3120,2283 -3089,2314 -3089,2388.04 J32.10@-3044.17,2432.87 ; v1(-3102.45,1571.73) -3044.27,1571.73 -3004.9,1611.1 v1(-2952.11,1611.1)
CAN1_RX_AWORKS: J32.7
CAN1_TX_AWORKS: J32.8
CTS/IO14_MICROP: J27.7 U2.10 U5.14 | length 3145
  Top Layer w6: v1(-2780,1581) -2774.79,1575.79 -2774.79,1519.89 U2.10@-2776.11,1518.58 U2.10@-2777.42,1517.26 ; U5.14@-2736.73,1458.54 -2736.73,1427.73 -2723,1414 v1(-2723,1400) -2715,1392 -2652,1392 -2604,1344 -2604,1271.23 -2638,1237.23 -2638,683 -2539.52,584.52 -2368.35,584.52 -2232.83,449 -1811,449 v1(-1724,536) ; v1(-1346,592) -1346,619 -1333,632 -874.49,632 J27.7@-852,654.48
  Bottom Layer w6: v1(-2780,1581) -2774.79,1575.79 -2774.79,1466.79 -2723,1415 v1(-2723,1400) ; v1(-1724,536) -1704,556 -1704,564 -1672,596 -1350,596 v1(-1346,592)
DAC/IO21_MICROP: J27.15
EARTH: C38.2 HOLE1.1 J1.6 J1.7 J1.8 J1.9 R106.2 | length 1023.7
  Top Layer w50: -300,2170 -330,2140 R106.2@-385,2140 C38.2@-385,2230 -295,2230 ; J1.6@-222.26,1817.81 J1.8@-85.65,1817.81 J1.9@-85.65,2101.27 ; -222.26,2197.74 J1.7@-222.26,2101.27 J1.9@-85.65,2101.27 ; -85.65,2194.35 J1.9@-85.65,2101.27
  other v1: -280,2195 -165,2205 -70,2220 -280,2275
GND: BT1.2 BZ1.2 C1.2 C2.2 C3.2 C4.2 C5.2 C7.2 C8.2 C9.2 C10.2 C11.2 C12.2 C13.2 C14.2 C15.2 C16.1 C17.1 C18.2 C19.2 C20.2 C21.2 C38.1 D1.1 D4.1 D5.1 ESD1.3 J1.5 J2.5 J4.3 J4.4 J27.1 J31.26 J32.23 J32.25 L2.1 R11.1 R15.1 R18.1 R106.1 S1.1 S1.4 S2.1 S2.4 T2.1 U1.2 U2.8 U2.23 U2.35 U2.47 U3.4 U3.5 U3.6 U3.7 U4.1 U5.12 U5.18 U5.31 U5.47 U5.63 X1.2 X1.4 | length 3017.5
  Top Layer w9.84: v1(-3114.88,1546.63) -3097.88,1546.63 -3092.47,1552.05 U5.63@-3066.46,1552.05 ; U2.47@-3006.42,1591.41 v1(-2970.43,1591.41) ; U5.47@-2972.95,1901.46 -2972.95,1927.55 -2977,1931.6 -2977,1951.72 v1(-2972.95,1955.77) ; v1(-2933.59,1805.42) U2.35@-2933.59,1841.41 ; U2.8@-2815.48,1518.58 v1(-2815.48,1573) ; v1(-2776.1,1404.12) U5.12@-2776.1,1458.54 ; v1(-2719.57,1768.58) U2.23@-2683.59,1768.58 ; U5.18@-2623.54,1552.05 -2597.53,1552.05 -2592.12,1546.63 v1(-2575.12,1546.63) ; U5.31@-2623.54,1807.95 v1(-2587.55,1807.95) ; v1@-900,1441 -900,1518
  Top Layer w15: v1(-3474,1448) -3475,1449 R18.1@-3475,1485 -3471,1489 v1(-3471,1536) ; v1(-3317.05,1487.95) D5.1@-3285,1487.95 D4.1@-3225,1487.95 -3208.95,1504 v1(-3195,1504) ; v1(-3216,1695) -3205,1684 C20.2@-3205,1665 v1(-3205,1640) C21.2@-3205,1615 ; v1@-3202,1394 -3165,1431 C8.2@-3165,1440 v1(-3129,1440) ; C19.2@-3060,1300 v1(-3032,1300) C14.2@-3005,1300 v1(-3005,1271) -3005,1240.16 X1.4@-2998.31,1233.46 -3010.54,1233.46 -3041.61,1202.39 -3041.61,1108.61 v1(-3039,1106) ; v1(-2880,1332) C15.2@-2880,1300 -2880,1286 v1(-2861,1267) ; v1(-2795,1270) C17.1@-2795,1300 ; C1.2@-995,1790 -980,1805 C2.2@-980,1860 ; J4.4@-850.3,2301.23 J4.3@-850.3,2401.23 ; -717,1589 -702.5,1574.5 D1.1@-702.5,1550
  Top Layer w20: C12.2@-2990,1985 -2972.95,1967.95 v1(-2972.95,1955.77) ; v1(-2580,2156) -2430,2006 C7.2@-2430,1970 v1(-2430,1926) -2451,1905 v1(-2453,1905) C10.2@-2480,1905 ; v1(-2480,1525) C11.2@-2480,1555 ; -2312.01,293 J31.26@-2244.17,225.15 ; C5.2@-1145,1990 -1131,2004 v1(-1123,2004) -1094,2004 C4.2@-1090,2000 v1(-1090,2056) ; U1.2@-905,1970 v1(-865,1970)
  Top Layer w30: U4.1@-372.5,1993 -347.42,2018.08 v1(-312,2018.08) v1(-287,2018.08) J1.5@-226,2018.08
  Bottom Layer w9.84: -2293,93 -2293,176.32 J31.26@-2244.17,225.15
  Bottom Layer w15: -2382,2383 -2344.17,2345.17 J32.23@-2344.17,2332.87 -2344.17,2295.17 -2320,2271 ; J31.26@-2244.17,225.15 -2200.01,181 ; J4.3@-850.3,2401.23 J4.4@-850.3,2301.23 -850.3,2277.3 -812,2239
  Bottom Layer w30: -949.48,54.48 J27.1@-852,54.48 -782.48,54.48
  other v1: -1860,31 -2595,32 -3401,36 -1743,39 -2372,44 -1240,50 -2476,53 -1564,54 -2118,60 -3321,63 -718,66 -3557,68 -3094,74 -2992,74 -491,99 -2186,127 -910,133 -2167,149 -1501,151 -1107,166 -790,178 -1770,198 -2071,206 -1003,233 -2154,257 -1855,295 -1299,307 -3862,329 -3475,367 -743,385 -384,387 -1186,409 -103,409 -2091,423 -2175,426 -2576,435 -1746,437 -1427,439 -2890,440 -582,442 -2755,444.48 -2338,449.48 -1713,493 -775,498 -1184,504 -1413,516 -1322,554 -2490,557 -553,566 -3558,573 -2635,575 -937,576 -3806,578 -1230,591 -2037,611 -3217,615 -720,649 -1379,658 -2219,661 -987,676 -1283,682 -2890,685 -1211,689 -3510,694 -1739,701 -1106,715 -2433,734 -424,767 -1923,775 -908,780 -3228,785 -87,786 -1179,806 -1107,811 -1011,811 -794,812 -2331,816 -2454,831 -2400,833 -3448,839 -1343,853 -707,854 -2690,855 -912,859 -1103,877 -984,882 -3497,889 -1217,890 -1743,903 -1985,910 -2237,923 -3861,926 -2870,930 -1100,930 -294,931 -3306,932 -3619,936 -3411,938 -2478,984 -551,986 -1225,1020 -3519,1032 -1152,1034 -2690,1045 -1076,1045 -1343,1046 -1820,1050 -1674,1050 -3007,1054 -2472,1057 -2801,1061 -681,1067 -828,1068 -999,1074 -3570,1081 -1452,1086 -3459,1090 -2005,1092 -1930,1095 -1264,1104 -2914,1107 -3169,1108 -2680,1140 -2808,1144 -2855,1153 -2235,1153 -751,1167 -996,1171 -3726,1176 -183,1183 -2690,1185 -1800,1193 -3230,1202 -2430,1202 -2001,1203 -1643,1204 -1724,1212 -520,1213 -693,1235 -1148,1277 -3882,1287 -3607,1287 -1445,1291 -1350,1294 -3487,1296 -3242,1297 -1697,1298 -883,1299 -1259,1302 -1076,1313 -2236,1319 -1997,1338 -2533,1339 -3161,1341 -1016,1346 -2657,1347 -2682,1369 -1835,1369 -3108,1373 -2336,1376 -738,1380 -3200,1392 -3477,1408 -1888,1409 -2608,1417 -967,1425 -3570,1427 -897,1434 -2528,1436 -2659,1438 -2090,1439 -3061,1474 -771,1480 -2333,1486 -2215,1493 -704,1502 -541,1506 -1850,1512 -3874,1547 -3641,1552 -2007,1582 -753,1585 -406,1587 -2278,1602 -1798,1603 -583,1662 -55,1667 -3529,1681 -711,1685 -2304,1690 -1406,1693 -1325,1697 -921,1697 -2179,1703 -689,1713 -1024,1719 -2082,1724 -1830,1731 -751,1745 -1963,1764 -492,1774 -3832,1778 -1071,1781 -1653,1794 -330,1797 -1207,1809 -3515,1836 -3020,1850 -1049,1851 -715,1854 -1855,1857 -2667,1866 -580,1870 -1428,1877 -1170,1879 -495,1880 -860,1884 -1535,1888 -3447,1898 -968,1902 -2562,1904 -3065,1925 -2279,1925 -2157,1926 -803,1928 -2030,1934 -3150,1940 -3422,1955 -953,1972 -3701,1978 -3535,1978 -300,1980 -3843,1989 -2602,1993 -735,1996 -761,2017 -3065,2035 -3398,2058 -1235,2065 -835,2070 -515,2075 -2956,2084 -1646,2103 -1546,2103 -673,2103 -1150,2107 -3555,2109 -898,2109 -1426,2111 -1391,2111 -2334,2117 -555,2125 -2053,2142 -2227,2147 -1875,2147 -2702,2163 -2367,2169 -3867,2176 -3266,2190 -555,2195 -785,2203 -1173,2235 -2790,2242 -3397,2246 -1100,2247 -2965,2259 -1391,2260 -555,2260 -3633,2266 -500,2290 -1810,2291 -395,2362.21 -2694,2381 -2117,2434 -2594,2460 -2694,2461 -1003,2461 -741,2466 -3837,2488 -2481,2488 -3194,2489 -602,2502 -400,2505 -1757,2506 -2327,2510 -3543,2522
HPR_AWORKS: J31.24
I2C1_SCL_1: J11.1 J27.12 J31.16 R28.2 | length 4361
  Top Layer w6: R28.2@-3245,1345 -3306,1284 -3306,1166 -3194,1054 -3049,1054 -2965,970 -2965,445.99 J31.16@-2744.17,225.15 ; J27.12@-1052,954.48 -1052,1392 -1001,1443 -1001,1536 J11.1@-1050,1585
  Bottom Layer w6: J31.16@-2744.17,225.15 -2744.17,255.83 -2655.48,344.52 -2051.14,344.52 -2008.14,387.52 -1824.03,387.52 -1733.52,297 -1472,297 -1052,717 J27.12@-1052,954.48
I2C1_SDA_1: J13.1 J27.13 J31.15 R29.2 | length 4930.8
  Top Layer w6: R29.2@-3290,1345 -3290,1325 -3322,1293 -3322,1161 -3199,1038 -3058,1038 -2985,965 -2985,440 -2793,248 -2793,173.99 J31.15@-2744.17,125.15 ; J27.13@-1152,954.48 -1100,1006.49 -1100,1619 -1089,1630 -995,1630 J13.1@-950,1585
  Bottom Layer w6: J31.15@-2745,117 -2757,117 -2816,176 -2860,176 -2887,203 -2887,260 -2861,286 -2740,286 -2666.48,359.52 -2057.35,359.52 -2014.35,402.52 -1813.52,402.52 -1723,312 -1480,312 -1152,640 J27.13@-1152,954.48
I2C2_SCL_1: J4.17 R9.2 | length 1180
  Top Layer w6: R9.2@-2395,1770 -2372,1770 -2277,1865 -2030,1865 -1735,2160 -1735,2198 -1694,2239 -1694,2327 -1671,2350 -1601.53,2350 J4.17@-1550.3,2401.23
I2C2_SDA_1: J4.19 R23.2 | length 1169.5
  Top Layer w6: R23.2@-2480,1815 -2457,1838 v1(-2358,1838) ; v1(-2298,1879) -2036,1879 -1753,2162 -1753,2210 -1707,2256 -1707,2344.53 J4.19@-1650.3,2401.23
  Bottom Layer w6: v1(-2358,1838) -2310,1838 -2298,1850 v1(-2298,1879)
LED0_3: J9.2 R3.2 | length 401.1
  Top Layer w6: R3.2@-1470,1795 -1300,1625 -1300,1548 -1250,1498 J9.2@-1250,1485
LED1_3: J10.2 R4.2 | length 384.6
  Top Layer w6: R4.2@-1330,1795 -1202,1667 -1202,1544 -1150,1492 J10.2@-1150,1485
MIC_AWORKS: J31.22
MISO_AWORKS: J32.3 U2.27 U5.35 | length 1120.5
  Top Layer w6: J32.3@-3344.17,2332.87 -3262.3,2251 -3216,2251 -3175.27,2210.27 -2852.01,2210.27 -2736.74,2095 v1(-2736.74,1937.44) U5.35@-2736.73,1901.46 ; v1(-2776.11,1787.1) U2.27@-2776.11,1841.41
  Bottom Layer w6: v1(-2776.11,1787.1) -2776.11,1885.89 -2736.74,1925.26 v1(-2736.74,1937.44)
MOSI_AWORKS: J32.4 U2.28 U5.36 | length 1310.2
  Top Layer w6: J32.4@-3344.17,2432.87 -3344.17,2411.83 -3392,2364 -3392,2316 -3311,2235 -3223,2235 -3185.27,2197.27 -2857.4,2197.27 -2756.43,2096.3 v1(-2756.43,1955.76) U5.36@-2756.43,1915 ; v1(-2808,1779) -2795.79,1791.21 U2.28@-2795.79,1841.41
  Bottom Layer w6: v1(-2808,1779) -2795.79,1791.21 -2795.79,1887.21 -2756.43,1926.57 v1(-2756.43,1955.76)
NCS0_AWORKS: J32.2 U2.25 U5.33 | length 1316.3
  Top Layer w6: J32.2@-3444.17,2432.87 -3384.04,2493 -3231,2493 -3193,2455 -3193,2278 -3151.27,2236.27 -2841.24,2236.27 -2698.05,2093.08 -2698.05,1902.14 U5.33@-2697.36,1901.46 -2697.36,1867.64 -2723.58,1841.42 U2.25@-2736.74,1841.41
NetBT1_1: BT1.1 D3.2 | length 100.9
  Top Layer w20: BT1.1@-3550,985 -3494.9,985 D3.2@-3462.5,952.6
NetBZ1_1: BZ1.1 D1.2 Q1.3 | length 405.4
  Top Layer w9.84: Q1.3@-655,1482.5 -655,1500 -607.5,1547.5 D1.2@-607.5,1550 -308.74,1550 BZ1.1@-295,1563.74
NetC3_1: C3.1 U1.4 | length 77.1
  Top Layer w6: U1.4@-1015,2007.4 -980,2042.4 C3.1@-980,2070
NetC4_1: C4.1 C5.1 R16.1 U1.5 | length 193.1
  Top Layer w30: R16.1@-1200,1940 C4.1@-1090,1940 -1082,1940 -1074.6,1932.6 U1.5@-1015,1932.6 U1.5@-1010,1932.6
NetC13_1: C13.1 D2.1 ESD1.1 ESD1.2 J8.2 R12.1 S1.2 S1.3 | length 2110.5
  Top Layer w6: J8.2@-1350,1485 -1302,1437 -1302,920 -1236,854 -964,854 -917,901 -808,901 -756,849 -756,771.1 ESD1.1@-692.4,707.5 ESD1.2@-617.6,707.5 -617.6,662.4 C13.1@-635,645 R12.1@-635,600 -635,567.5 D2.1@-607.5,540 S1.2@-475,540 S1.3@-125,540
NetC18_1: C18.1 R26.2 X2.2 | length 131.5
  Top Layer w6: X2.2@-3179.21,1180 -3195,1195.79 C18.1@-3195,1260 R26.2@-3150,1260
NetC19_1: C19.1 R27.2 X2.1 | length 133.6
  Top Layer w6: R27.2@-3105,1260 C19.1@-3060,1260 -3060,1218 -3080.67,1197.33 X2.1@-3080.67,1180
NetJ1_1: J1.1 L7.2 | length 178.4
  Top Layer w30: L7.2@-375,1830 -357,1830 -286,1901 J1.1@-226,1901
NetJ14_2: J14.2 S2.2 S2.3 | length 1033.8
  Top Layer w6: J14.2@-850,1485 -792,1427 -792,1271 -481,960 S2.2@-475,960 S2.3@-125,960
NetJ14_3: J14.3 R7.2 | length 1392.3
  Top Layer w6: R7.2@-2113.01,1376.48 -2042.49,1447 -1764,1447 v1(-1734,1417)
  Bottom Layer w6: v1(-1734,1417) -1734,1379 -1677,1322 -1539,1322 -1476,1385 J14.3@-850,1385
NetL8_2: L8.2 R21.1 | length 72.2
  Top Layer w6: L8.2@-621.54,1929.25 -598.75,1929.25 -588,1940 -575,1940 R21.1@-560,1925
NetL8_3: L8.3 R22.2 | length 72.6
  Top Layer w6: L8.3@-621.54,1960.75 -599.75,1960.75 -591,1952 -578,1952 R22.2@-560,1970
NetLED0_2: LED0.2 R3.1 | length 100
  Top Layer w6: R3.1@-1470,1835 LED0.2@-1470,1932.32 LED0.2@-1470,1935
NetLED1_2: LED1.2 R4.1 | length 100
  Top Layer w6: R4.1@-1330,1835 LED1.2@-1330,1932.32 LED1.2@-1330,1935
NetLED2_2: LED2.2 R15.2 | length 100
  Top Layer w6: R15.2@-1610,1835 LED2.2@-1610,1932.32 LED2.2@-1610,1935
NetQ1_1: Q1.1 R1.1 R2.1 | length 109.7
  Top Layer w6: Q1.1@-692.4,1397.5 -692.4,1357.4 R2.1@-675,1340 R1.1@-675,1295
NRST_7: C17.2 R25.2 U2.7 U5.7 | length 411.8
  Top Layer w6: U5.7@-2874.53,1458.54 -2874.53,1423.55 v1(-2876.53,1421.55) -2876.53,1388.53 -2835,1347 C17.2@-2835,1300 -2835,1260 R25.2@-2830,1255 ; v1(-2837.16,1555.58) -2835.16,1553.58 U2.7@-2835.16,1518.58
  Bottom Layer w6: v1(-2876.53,1421.55) -2837.16,1460.91 v1(-2837.16,1555.58)
OSC_IN_7: C14.1 U2.5 U5.5 X1.1 | length 528.3
  Top Layer w6: X1.1@-2998.31,1166.54 -2988.46,1166.54 -2956,1199 -2956,1291 C14.1@-2965,1300 -2965,1305 -2915.9,1354.1 v1(-2915.9,1421.55) -2913.9,1423.55 U5.5@-2913.9,1458.54 ; v1(-2876.53,1555.53) -2874.53,1553.53 U2.5@-2874.53,1518.58
  Bottom Layer w6: v1(-2915.9,1421.55) -2915.9,1435.1 -2876.53,1474.47 v1(-2876.53,1555.53)
OSC_OUT_7: C15.1 U2.6 U5.6 X1.3 | length 487.3
  Top Layer w6: X1.3@-2911.69,1233.46 -2920,1241.77 C15.1@-2920,1300 -2920,1330 -2896.21,1353.79 v1(-2896.21,1403.23) -2895.53,1403.92 -2895.53,1457.23 U5.6@-2894.21,1458.54 ; U2.6@-2854.85,1518.58 -2856.16,1519.89 -2856.16,1574.53 v1(-2854.85,1575.85)
  Bottom Layer w6: v1(-2896.21,1403.23) -2896.21,1429.79 -2856.16,1469.84 -2856.16,1574.53 v1(-2854.85,1575.85)
PA1/USART2_RTS: J27.6 U2.11 U5.15 | length 3018.5
  Top Layer w6: U2.11@-2756.42,1518.58 v1@-2756.42,1553.58 ; U5.15@-2717.05,1458.54 -2717.05,1431.05 v1(-2701,1415) -2652,1415 -2586,1349 -2586,1269.43 -2624,1231.43 -2624,688.8 -2533.72,598.52 -2362.55,598.52 -2227.03,463 -1829,463 v1(-1726,566) ; v1(-1322,613) -910.52,613 J27.6@-852,554.48
  Bottom Layer w6: v1(-2755.42,1553.58) -2755.42,1469.42 v1(-2701,1415) ; v1@-2754.42,1553.58 v1@-2754.42,1555.58 ; v1(-1726,566) -1679,613 v1(-1322,613)
PA8_1: J4.11 J27.24 J31.13 U2.29 U5.41 | length 6465
  Top Layer w6: U5.41@-2854.84,1901.46 v1(-2854.84,1955.77) v1(-2854.84,2083.84) -2854.84,2093.84 -2890,2129 -3165.77,2129 -3326,1968.77 -3326,1767 -3353,1740 -3353,1153 -3210,1010 -3080,1010 -3018,948 -3018,380.6 -2893,255.6 -2893,173.99 J31.13@-2844.17,125.15 ; v1(-2815.48,1805.42) U2.29@-2815.48,1841.41 ; v1(-1337.84,2083.84) -1303,2118.69 -1303,2348.53 J4.11@-1250.3,2401.23
  Bottom Layer w6: v1(-2854.84,1955.77) -2854.84,1920.84 -2815.48,1881.48 v1(-2815.48,1805.42) ; v1(-2854.84,2083.84) v1(-1337.84,2083.84) ; J31.13@-2844.17,125.15 -2903.26,184.25 -2903.26,266.74 -2867.74,302.26 -2746.74,302.26 -2675,374 -2063.35,374 -2020.35,417 -1806,417 -1743.48,354.48 J27.24@-1652,354.48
